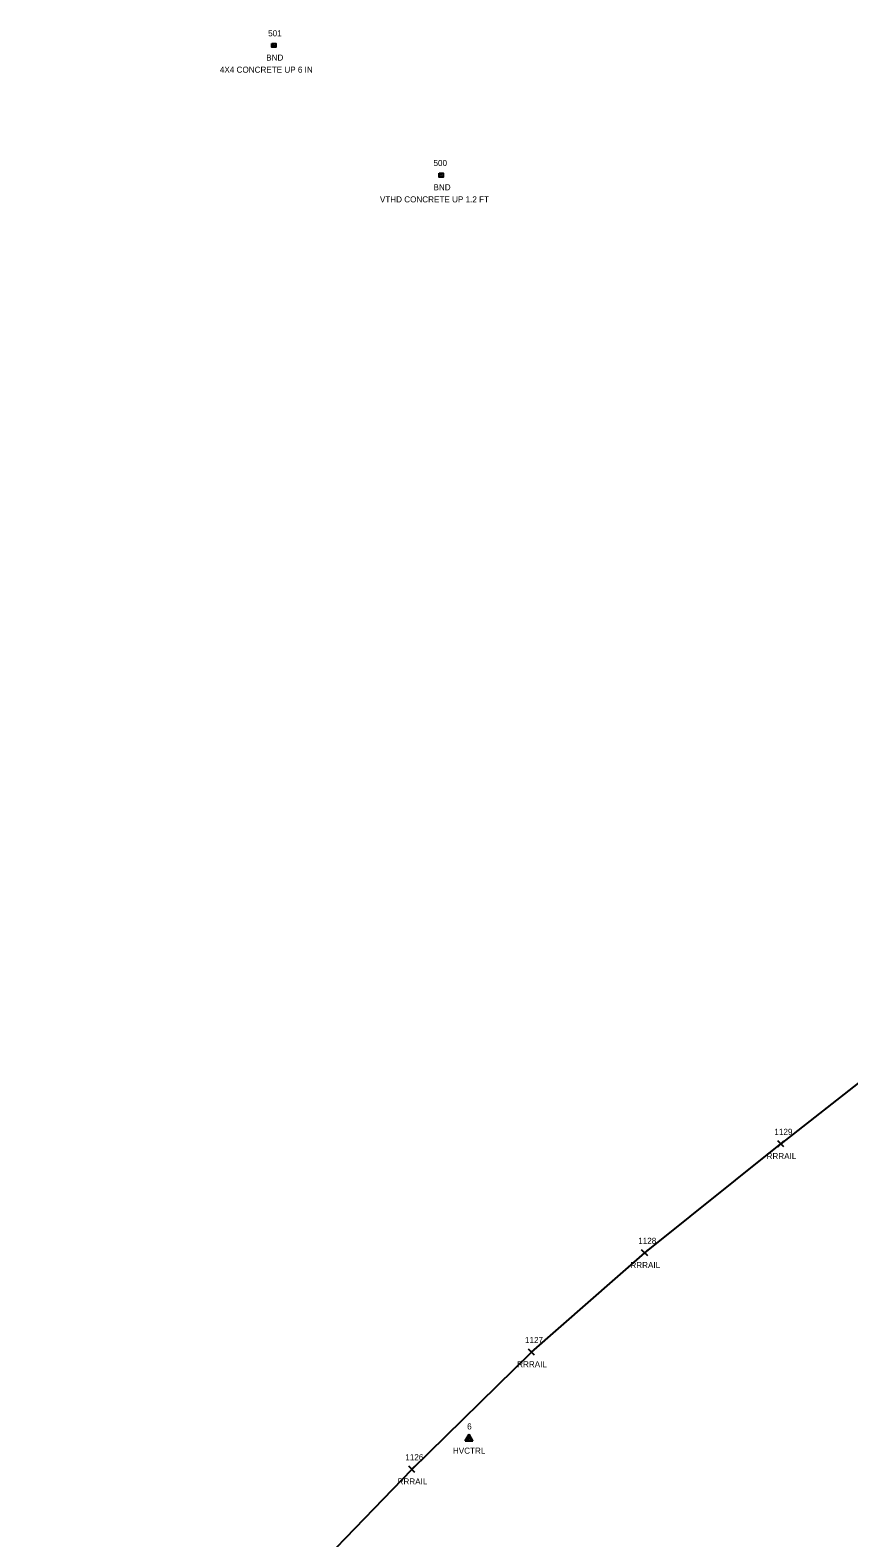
# Model space of a CAD drawing. Extents: x 1764889 to 1767296, y 695936 to 698960.
# Drawn here: x 1765861.9 to 1766131.8, y 696220.7 to 696717.9 of the extents above; entities that cross this region are included whole.
import ezdxf

# ---------------------------------------------------------------- set-up
doc = ezdxf.new("R2010")
doc.units = 0
for name, color, linetype in [('C_A', 7, 'Continuous'), ('C_I', 7, 'Continuous'), ('CPSM', 7, 'Continuous'), ('Level 18', 7, 'Continuous'), ('M_A', 7, 'Continuous'), ('M_C', 7, 'Continuous'), ('M_I', 7, 'Continuous'), ('R_A', 7, 'Continuous'), ('R_I', 7, 'Continuous'), ('R_TIC', 7, 'Continuous'), ('RR', 7, 'Continuous')]:
    doc.layers.add(name, color=color, linetype=linetype)

msp = doc.modelspace()

# ---------------------------------------------------------------- linework, layer by layer
at = {"layer": 'CPSM'}
for p, q in [((1766005.35, 696252.74), (1766006.6, 696254.9)), ((1766005.35, 696252.74), (1766006.6, 696254.9)), ((1766005.35, 696252.74), (1766006.6, 696254.9)), ((1766005.35, 696252.74), (1766006.6, 696253.46)), ((1766005.35, 696252.74), (1766006.6, 696253.46)), ((1766005.35, 696252.74), (1766006.6, 696253.46)), ((1766005.35, 696252.74), (1766007.85, 696252.74)), ((1766005.35, 696252.74), (1766007.85, 696252.74)), ((1766005.35, 696252.74), (1766007.85, 696252.74)), ((1766007.85, 696252.74), (1766006.6, 696254.9)), ((1766006.6, 696253.46), (1766006.6, 696254.9)), ((1766007.85, 696252.74), (1766006.6, 696254.9)), ((1766006.6, 696253.46), (1766006.6, 696254.9)), ((1766007.85, 696252.74), (1766006.6, 696254.9)), ((1766006.6, 696253.46), (1766006.6, 696254.9)), ((1766006.6, 696253.46), (1766006.6, 696253.46)), ((1766006.6, 696253.46), (1766007.85, 696252.74)), ((1766006.6, 696253.46), (1766006.6, 696253.46)), ((1766006.6, 696253.46), (1766007.85, 696252.74)), ((1766006.6, 696253.46), (1766006.6, 696253.46)), ((1766006.6, 696253.46), (1766007.85, 696252.74))]:
    msp.add_line(p, q, dxfattribs=at)
at = {"layer": 'Level 18'}
for points in [[(1765941.63, 696713.5), (1765942.88, 696713.5), (1765942.88, 696712.25), (1765941.63, 696712.25)], [(1765996.79, 696670.72), (1765998.04, 696670.72), (1765998.04, 696669.47), (1765996.79, 696669.47)]]:
    msp.add_lwpolyline(points, close=True, dxfattribs=at)
for centre in [(1765942.25, 696712.87), (1765997.41, 696670.1)]:
    msp.add_circle(centre, 0.0833, dxfattribs=at)
at = {"layer": 'R_TIC'}
for points in [[(1766108.4, 696349.61), (1766110.4, 696351.61)], [(1766110.4, 696349.61), (1766108.4, 696351.61)], [(1766108.4, 696349.61), (1766110.4, 696351.61)], [(1766110.4, 696349.61), (1766108.4, 696351.61)], [(1766063.51, 696313.67), (1766065.51, 696315.67)], [(1766065.51, 696313.67), (1766063.51, 696315.67)], [(1766026.17, 696280.97), (1766028.17, 696282.97)], [(1766028.17, 696280.97), (1766026.17, 696282.97)], [(1765986.77, 696242.31), (1765988.77, 696244.31)], [(1765988.77, 696242.31), (1765986.77, 696244.31)]]:
    msp.add_lwpolyline(points, dxfattribs=at)
at = {"layer": 'RR'}
for points in [[(1766299.86, 696528.94), (1766277.75, 696500.06), (1766257.52, 696477.14), (1766236.01, 696454.81), (1766202.65, 696425.22), (1766159.82, 696390.23), (1766109.4, 696350.61)], [(1765861.93, 696112.49), (1765902.5, 696153.66), (1765950.39, 696204.51), (1765987.77, 696243.31), (1766027.17, 696281.97), (1766064.51, 696314.67), (1766109.4, 696350.61)]]:
    msp.add_lwpolyline(points, dxfattribs=at)

# ---------------------------------------------------------------- texts
at = {"layer": 'C_A'}
msp.add_text('HVCTRL', height=2, dxfattribs=at).set_placement((1766001.29, 696248.46))
msp.add_text('HVCTRL', height=2, dxfattribs=at).set_placement((1766001.29, 696248.46))
msp.add_text('HVCTRL', height=2, dxfattribs=at).set_placement((1766001.29, 696248.46))
at = {"layer": 'C_I'}
msp.add_text('6', height=2, dxfattribs=at).set_placement((1766005.98, 696256.46))
msp.add_text('6', height=2, dxfattribs=at).set_placement((1766005.98, 696256.46))
msp.add_text('6', height=2, dxfattribs=at).set_placement((1766005.98, 696256.46))
at = {"layer": 'M_A'}
for p in [(1765939.74, 696707.87), (1765994.9, 696665.1)]:
    msp.add_text('BND', height=2, dxfattribs=at).set_placement(p)
at = {"layer": 'M_C'}
for s, p in [('4X4 CONCRETE UP 6 IN', (1765924.48, 696703.87)), ('VTHD CONCRETE UP 1.2 FT', (1765977.23, 696661.1))]:
    msp.add_text(s, height=2, dxfattribs=at).set_placement(p)
at = {"layer": 'M_I'}
for s, p in [('501', (1765940.38, 696715.87)), ('500', (1765994.89, 696673.1))]:
    msp.add_text(s, height=2, dxfattribs=at).set_placement(p)
at = {"layer": 'R_A'}
for p in [(1766104.69, 696345.61), (1766104.69, 696345.61), (1766059.8, 696309.67), (1766022.47, 696276.97), (1765983.06, 696238.31)]:
    msp.add_text('RRRAIL', height=2, dxfattribs=at).set_placement(p)
at = {"layer": 'R_I'}
for s, p in [('1129', (1766107.26, 696353.61)), ('1129', (1766107.26, 696353.61)), ('1128', (1766062.38, 696317.67)), ('1127', (1766025.05, 696284.97)), ('1126', (1765985.59, 696246.31))]:
    msp.add_text(s, height=2, dxfattribs=at).set_placement(p)

doc.saveas('drawing.dxf')
